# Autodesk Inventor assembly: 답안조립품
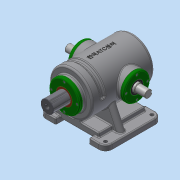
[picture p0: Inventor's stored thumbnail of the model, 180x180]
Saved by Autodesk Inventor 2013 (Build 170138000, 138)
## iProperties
Created: 2018-06
Part Number: 답안조립품
Document SubType Name: Assembly
Designer: Administrator
Author: Administrator
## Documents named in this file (13)
- C:\Users\Administrator\Desktop\380628V1003\답안조립품.iam
- C:\Users\Administrator\Desktop\380628V1003\본체.ipt
- C:\Users\Administrator\Desktop\380628V1003\가변스프링.ipt
- C:\Users\Administrator\Desktop\380628V1003\베어링 6205.ipt
- 베어링 6205.ipt
- C:\Users\Administrator\Desktop\380628V1003\볼트 M4.ipt
- C:\Users\Administrator\Desktop\380628V1003\부시.ipt
- C:\Users\Administrator\Desktop\380628V1003\슬라이드 커버.ipt
- C:\Users\Administrator\Desktop\380628V1003\슬라이드.ipt
- C:\Users\Administrator\Desktop\380628V1003\오일실.ipt
- 오일실.ipt
- C:\Users\Administrator\Desktop\380628V1003\축 커버.ipt
- C:\Users\Administrator\Desktop\380628V1003\편심축.ipt
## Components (1 placed, 1 different names)
1. 가변스프링:1
